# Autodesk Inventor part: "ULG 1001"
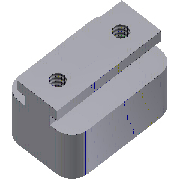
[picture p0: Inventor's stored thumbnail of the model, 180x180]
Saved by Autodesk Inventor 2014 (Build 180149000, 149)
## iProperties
IsCustomPart: 1
Created: 2009-11
Part Number: "ULG 1001"
Material: DIN 1.7225
Description: Gib
Document SubType Name: Modeling
Designer: gaom
Standard Revision: 1
Manufacturer: DME
Language: en-US
Size Designation: "1001"
Categories: <MemberInstance><Categories><Category DisplayName="Mold" InternalName="349578f2-f4d4-4954-8c09-8e99297a61c0" Mnemonic="MOLD"><Category DisplayName="Lifter Compo
Density: 100 g/cm^3
Appearance: Wheat
ULG_W: 22.000 mm
Author: gaom
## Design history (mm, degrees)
sketch "Sketch1"
  geometry: L1 (0, -15.6)-(0, 2.6) reference; L2 (0, 0)-(-6.25, 0); L3 (-6.25, 0)-(-6.25, -2); L4 (-6.25, -2)-(-4, -2); L5 (-4, -2)-(-4, -4); L6 (-4, -4)-(-11, -4); L7 (-11, -4)-(-11, -13); L8 (-11, -13)-(0, -13); L9 (11, -4)-(11, -13); L10 (11, -13)-(0, -13); L11 (4, -4)-(11, -4); L12 (4, -2)-(4, -4); L13 (6.25, -2)-(4, -2); L14 (6.25, 0)-(6.25, -2); L15 (0, 0)-(6.25, 0)
  constraints: 28 end point, 6 symmetric about line, 5 perpendicular, 2 parallel, 1 point on line
  dimensions: "d0" = 12.5 diameter of L3 L1 (= ULG_W1); "d2" = 8 diameter of L5 L1 (= ULG_W2); "d3" = 4 distance between parallel lines of L6 L2 (= ULG_H1); "d4" = 13 distance between parallel lines of L8 L2 (= H_); "d5" = 2 distance between parallel lines of L6 L4 (= ULG_H2); "d6" = 22 diameter of L7 L1 (= W_)
extrude "Extrusion1" new body sketch "Sketch1" distance "d7" = 33 (= L); taper "d8" = 0 deg
fillet "Fillet1" dims "d9" = 5 (= R)
fillet "Fillet2" dims "d38" = 0.3 (= a)
sketch "Sketch2"
  geometry: L1 (-6.6, 6.25)-(39.6, 6.25) reference; L2 (5, 17.25)-(28, 17.25) reference; L3 (16.5, 17.25)-(16.5, -4.75); L4 (5, -4.75)-(28, -4.75) reference; 2 further points
  constraints: 2 end point, 2 midpoint, 1 point on line
  dimensions: "d10" = 10 horizontal distance of L3.start point (6.5, 6.25) (= S_)
hole "Hole1" sketch "Sketch2" at (6.5, 6.25) diameter "d11" = 4.134; stored, may be unused: countersink angle "d15" = 90 deg, drill point angle "d17" = 0 deg; dims "d12" = 6, "d13" = 4, "d14" = 2, "d16" = 13 (= H_)
sketch "Sketch4"
  geometry: L1 (-33, 12)-(-33, 0) reference; L2 (-5, -5)-(-28, -5) reference; L3 (0, 0)-(0, 12) reference; L4 (-5, 17)-(-28, 17) reference; A1 r 5 centre (-28, 12) between (-28, 17) and (-33, 12) reference; A2 r 5 centre (-28, 0) between (-33, 0) and (-28, -5) reference; A3 r 5 centre (-5, 0) between (-5, -5) and (0, 0) reference; A4 r 5 centre (-5, 12) between (0, 12) and (-5, 17) reference; 1 further point
hole "Hole2" sketch "Sketch4" diameter "d30" = 4.134; stored, may be unused: countersink angle "d34" = 90 deg, drill point angle "d36" = 0 deg; dims "d31" = 6, "d32" = 4, "d33" = 2, "d35" = 13 (= H_)
feature "Stitch Surface1" dims "d39" = 0.254 (derived)
node "ULG_ULC"
node "Ground"
body "Solid1"
body "Srf1"
body "Srf2"
body "Srf3"
body "Srf4"
sketch "Sketch3"
  geometry: L1 (5, 17.25)-(28, 17.25) reference; L2 (16.5, 17.25)-(16.5, 1.648); L3 (0, 12.5)-(0, 0) reference; 3 further points
  constraints: 2 end point, 2 midpoint, 1 horizontal alignment, 1 perpendicular
  dimensions: "d29" = 10 distance from line of point (26.5, 6.25) L2 (= S_)
extrude_surface "ExtrusionSrf1" dims "d22" = 19.5 (= H_ + ULG_es1), "d23" = 0
patch "Boundary Patch1" dims "d24" = 0, "d25" = 0
patch "Boundary Patch2" dims "d26" = 0, "d27" = 0
other parameters: "W_" = 22 [user parameter; used in 1 equation term], "H_" = 13 [user parameter; used in 5 equation terms], "S_" = 10 [user parameter; used in 2 equation terms], "L" = 33 [user parameter; used in 1 equation term], "ULG_es1" = 6.5 (= 0.5 x H_) [user parameter; used in 1 equation term], "M" = 5 [user parameter], "ULG_W1" = 12.5 [user parameter; used in 1 equation term], "ULG_W2" = 8 [user parameter; used in 1 equation term], "ULG_H1" = 4 [user parameter; used in 1 equation term], "ULG_H2" = 2 [user parameter; used in 1 equation term], "d28" = 0, "R" = 5 [user parameter; used in 1 equation term], "d37" = 0, "a" = 0.3 [user parameter; used in 1 equation term]
